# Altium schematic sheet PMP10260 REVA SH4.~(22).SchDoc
size 431 x 279 mm; Date: Not shown in title block; ApprovedBy: Not shown in title block; CheckedBy: Not shown in title block; Author: Not shown in title block; CompanyName: Not shown in title block; Engineer: Not shown in title block; Organization: Not shown in title block; Address1: Not shown in title block; Address2: Not shown in title block; Address3: Not shown in title block; Address4: Not shown in title block; DocumentNumber: 4; Revision: Use project parameter SCH_Rev; SheetNumber: 4; SheetTotal: 4; PageSetup: Record=PageOptions|CenterHorizontal=True|CenterVertical=True|PrintScale=1.00|XCorrection=1.00|YCorrection=1.00|PrintKind=0|BorderSize=5000000|LeftOffset=0|BottomOffset=0|Orientation=2|PaperLength=1000|PaperWidth=1000|Scale=100|PaperSource=15|PrintQuality=600|MediaType=1|DitherType=10|PaperKind=Letter|PrintScaleMode=1
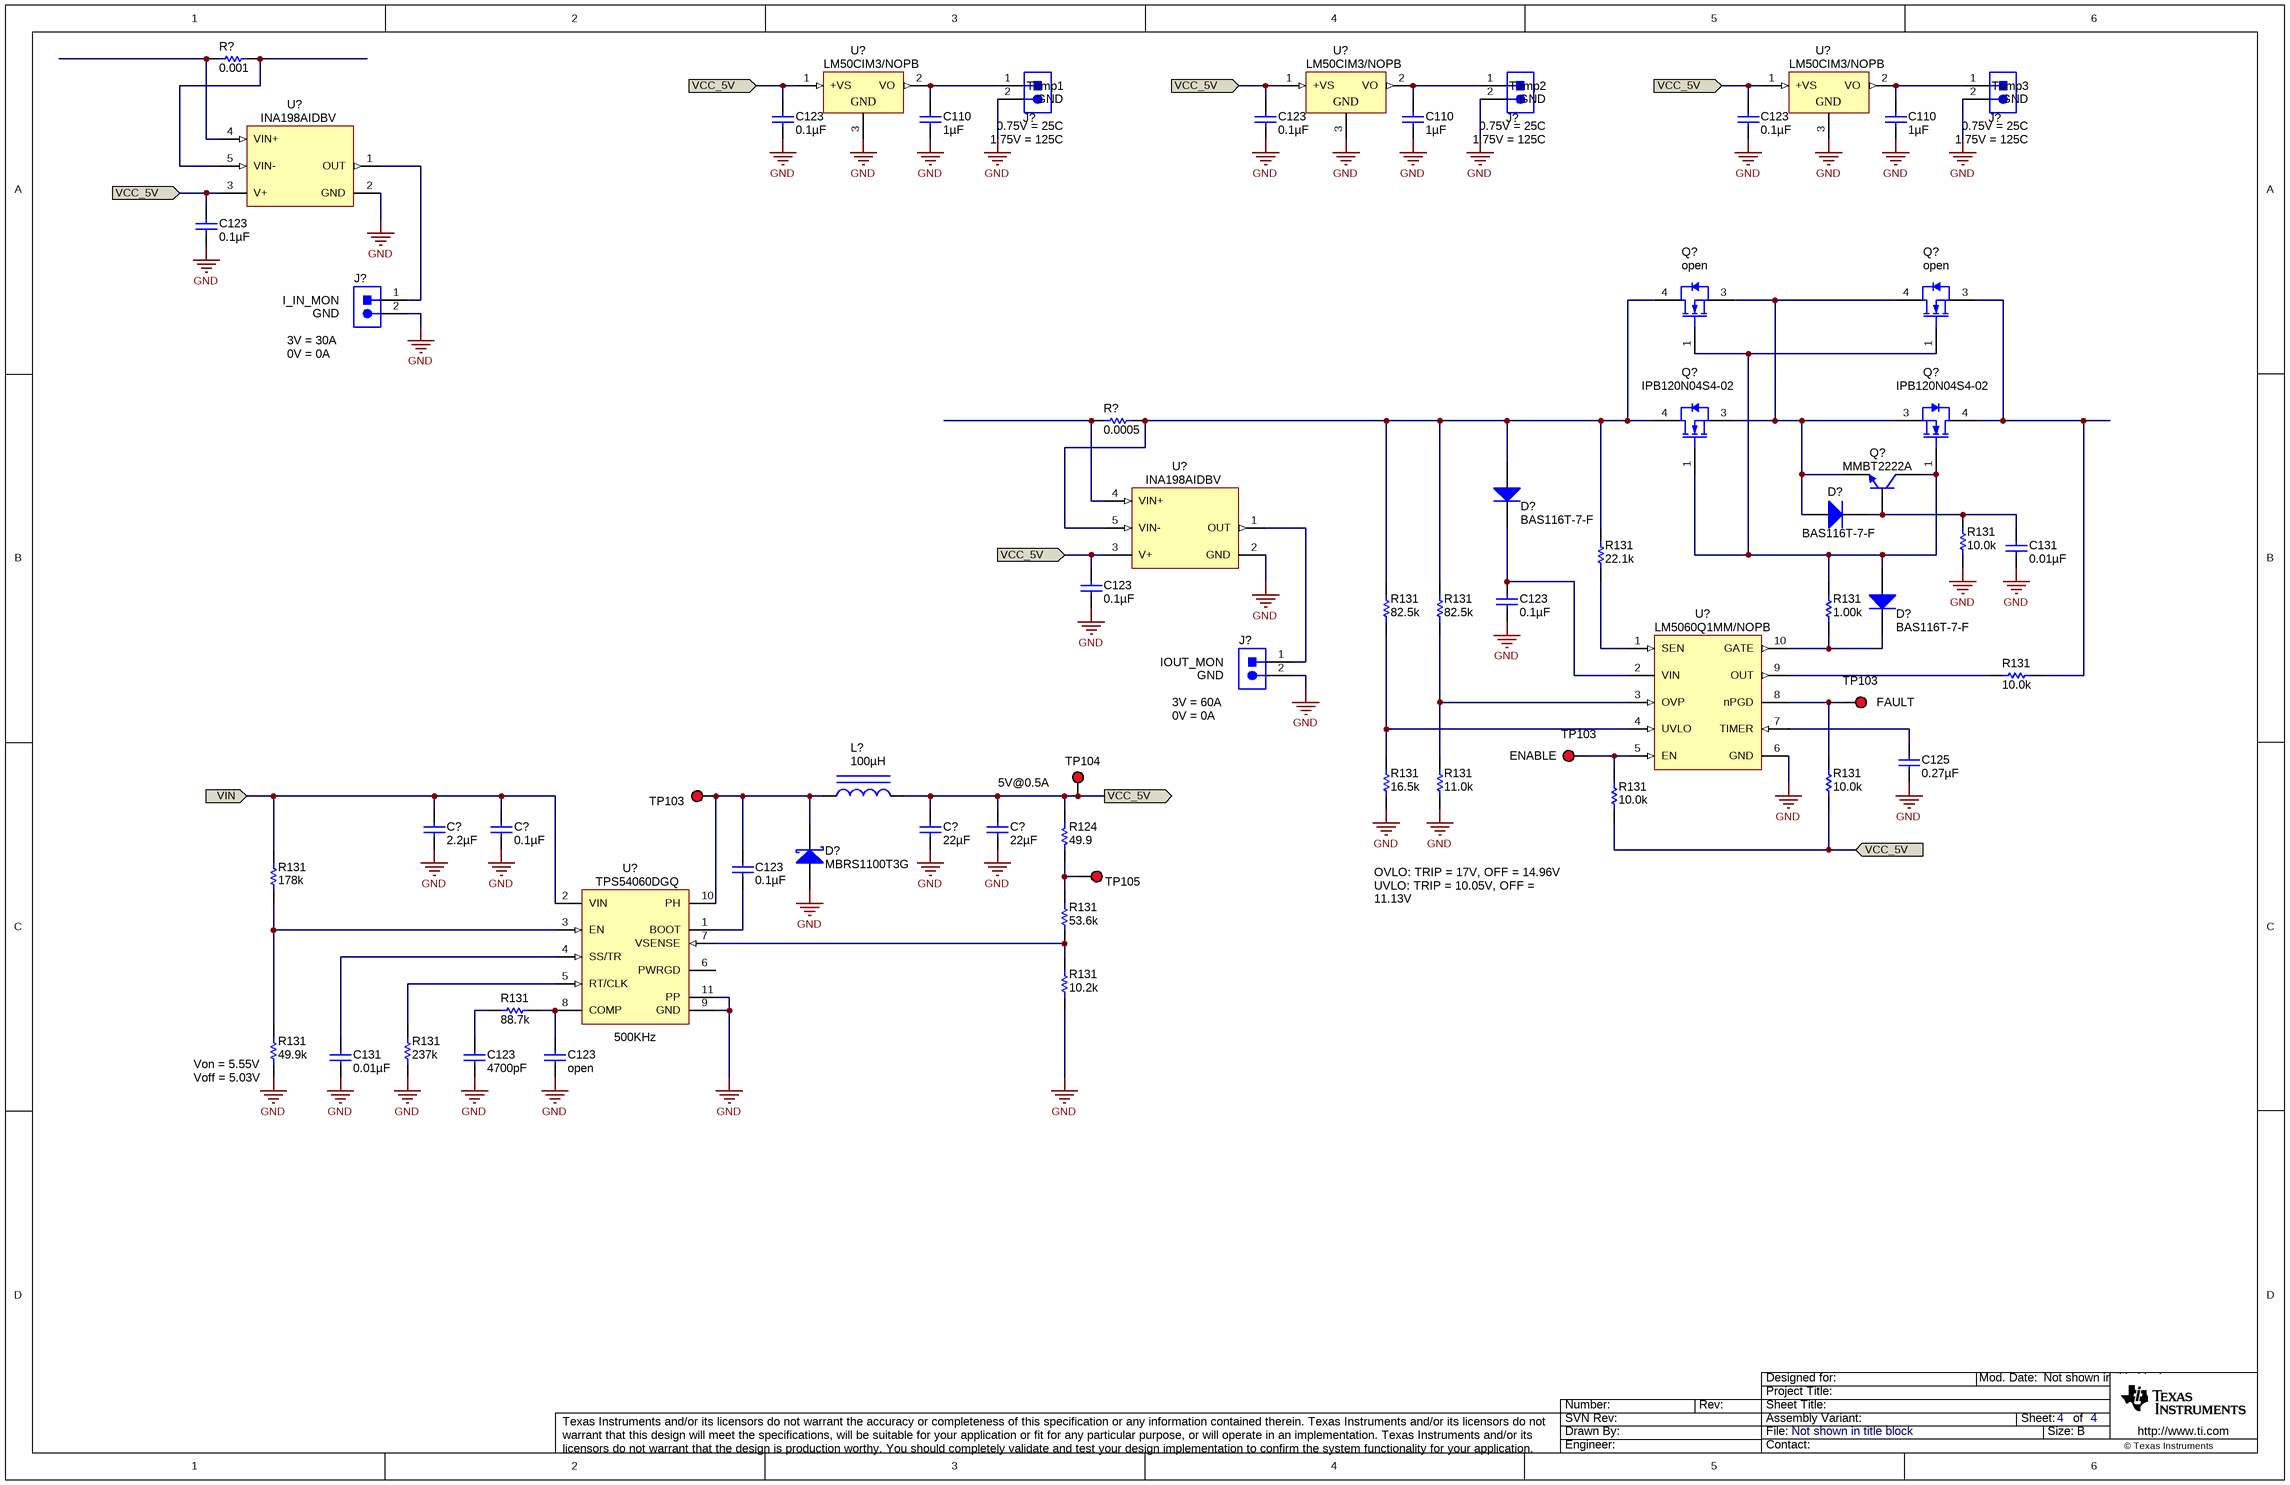
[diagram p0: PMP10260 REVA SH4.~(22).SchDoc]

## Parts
(Parts that share a designator on the sheet are numbered #1, #2 ... from top to bottom, then left to right.)
C110#1  ValueDisplayed: 1µF  [0603L]  (hidden comment: C1608X7R1E105K080AB)
C110#2  ValueDisplayed: 1µF  [0603L]  (hidden comment: C1608X7R1E105K080AB)
C110#3  ValueDisplayed: 1µF  [0603L]  (hidden comment: C1608X7R1E105K080AB)
C123#1  ValueDisplayed: 0.1µF  [0603L]  (hidden comment: C1608X7R1H104K)
C123#2  ValueDisplayed: 0.1µF  [0603L]  (hidden comment: C1608X7R1H104K)
C123#3  ValueDisplayed: 0.1µF  [0603L]  (hidden comment: C1608X7R1H104K)
C123#4  ValueDisplayed: 0.1µF  [0603L]  (hidden comment: C1608X7R1H104K)
C123#5  ValueDisplayed: 0.1µF  [0603L]  (hidden comment: C1608X7R1H104K)
C123#6  ValueDisplayed: 0.1µF  [0603L]  (hidden comment: C1608X7R1H104K)
C123#7  ValueDisplayed: 0.1µF  [0603L]  (hidden comment: C1608X7R1H104K)
C123#8  ValueDisplayed: 4700pF  [0603]  (hidden comment: C1608C0G1H472J)
C123#9  ValueDisplayed: open  [0603L]
C125  ValueDisplayed: 0.27µF  [0805_HV]  (hidden comment: 0805YC274KAT2A)
C131#1  ValueDisplayed: 0.01µF  [0603]  (hidden comment: C1608X7R1H103K)
C131#2  ValueDisplayed: 0.01µF  [0603]  (hidden comment: C1608X7R1H103K)
C?#1  ValueDisplayed: 2.2µF  [1210]  (hidden comment: GRM32ER72A225KA35L)
C?#2  ValueDisplayed: 0.1µF  [0603]  (hidden comment: GRM188R72A104KA35D)
C?#3  ValueDisplayed: 22µF  [1210]  (hidden comment: C3225X7R1C226M)
C?#4  ValueDisplayed: 22µF  [1210]  (hidden comment: C3225X7R1C226M)
D?#1  BAS116T-7-F  [SOT-523]
D?#2  BAS116T-7-F  [SOT-523]
D?#3  BAS116T-7-F  [SOT-523]
D?#4  MBRS1100T3G  [SMB]
J?#1  PEC02SAAN  [CONN_PEC02SAAN]  (value not drawn)
J?#2  PEC02SAAN  [CONN_PEC02SAAN]  (value not drawn)
J?#3  PEC02SAAN  [CONN_PEC02SAAN]  (value not drawn)
J?#4  PEC02SAAN  [CONN_PEC02SAAN]  (value not drawn)
J?#5  PEC02SAAN  [CONN_PEC02SAAN]  (value not drawn)
L?  ValueDisplayed: 100µH  [MSS1048]  (hidden comment: MSS1048-104MLB)
Q?#1  open  [DDPAK]
Q?#2  open  [DDPAK]
Q?#3  IPB120N04S4-02  [DDPAK]
Q?#4  IPB120N04S4-02  [DDPAK]
Q?#5  MMBT2222A  [SOT-23]
R124  value 49.9  [0603]  (hidden comment: CRCW060349R9FKEA)
R131#1  value 10.0k  [0603]  (hidden comment: CRCW060310K0FKEA)
R131#2  value 22.1k  [0603]  (hidden comment: CRCW060322K1FKEA)
R131#3  value 82.5k  [0603]  (hidden comment: CRCW060382K5FKEA)
R131#4  value 82.5k  [0603]  (hidden comment: CRCW060382K5FKEA)
R131#5  value 1.00k  [0603]  (hidden comment: CRCW06031K00FKEA)
R131#6  value 10.0k  [0603]  (hidden comment: CRCW060310K0FKEA)
R131#7  value 16.5k  [0603]  (hidden comment: CRCW060316K5FKEA)
R131#8  value 11.0k  [0603]  (hidden comment: CRCW060311K0FKEA)
R131#9  value 10.0k  [0603]  (hidden comment: CRCW060310K0FKEA)
R131#10  value 10.0k  [0603]  (hidden comment: CRCW060310K0FKEA)
R131#11  value 178k  [0603]  (hidden comment: CRCW0603178KFKEA)
R131#12  value 53.6k  [0603]  (hidden comment: CRCW060353K6FKEA)
R131#13  value 10.2k  [0603]  (hidden comment: CRCW060310K2FKEA)
R131#14  value 88.7k  [0603]  (hidden comment: CRCW060388K7FKEA)
R131#15  value 49.9k  [0603]  (hidden comment: CRCW060349K9FKEA)
R131#16  value 237k  [0603]  (hidden comment: CRCW0603237KFKEA)
R?#1  value 0.001  [CSS2725_0005]  (hidden comment: CSS2725FT1L00)
R?#2  value 0.0005  [CSS2725_0005]  (hidden comment: CSS2725FTL500)
TP103#1  5010  [Keystone5010]  (value not drawn)
TP103#2  5010  [Keystone5010]  (value not drawn)
TP103#3  5010  [Keystone5010]  (value not drawn)
TP104  5010  [Keystone5010]  (value not drawn)
TP105  5010  [Keystone5010]  (value not drawn)
U?#1  LM50CIM3/NOPB  [MF03A_N]
U?#2  LM50CIM3/NOPB  [MF03A_N]
U?#3  LM50CIM3/NOPB  [MF03A_N]
U?#4  INA198AIDBV  [DBV0005A_N]
U?#5  INA198AIDBV  [DBV0005A_N]
U?#6  LM5060Q1MM/NOPB  [MUB10A_N]
U?#7  TPS54060DGQ  [DGQ0010D_N]

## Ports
VCC_5V, VIN

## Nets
GND: C110#1.2 C110#2.2 C110#3.2 C123#1.2 C123#2.2 C123#3.2 C123#4.2 C123#5.2 C123#6.2 C123#8.2 C123#9.2 C125.2 C131#1.2 C131#2.2 C?#1.2 C?#2.2 C?#3.2 C?#4.2 D?#4.2(A) J?#1.2 J?#2.2 J?#3.2 J?#4.2 J?#5.2 R131#1.1 R131#7.1 R131#8.1 R131#13.1 R131#15.1 R131#16.1 U?#1.3(GND) U?#2.3(GND) U?#3.3(GND) U?#4.2(GND) U?#5.2(GND) U?#6.6(GND) U?#7.9(GND) U?#7.11(PP)
VCC_5V: C123#1.1 C123#2.1 C123#3.1 C123#4.1 C123#5.1 C?#3.1 C?#4.1 L?.2 R124.2 R131#9.1 R131#10.1 TP104.1 U?#1.1(+VS) U?#2.1(+VS) U?#3.1(+VS) U?#4.3(V+) U?#5.3(V+) ; port VCC_5V
VIN: C?#1.1 C?#2.1 R131#11.2 U?#7.2(VIN) ; port VIN
NetC110#1_1: C110#1.1 J?#1.1 U?#1.2(VO)
NetC110#2_1: C110#2.1 J?#2.1 U?#2.2(VO)
NetC110#3_1: C110#3.1 J?#3.1 U?#3.2(VO)
NetC123#6_1: C123#6.1 D?#1.3(K) U?#6.2(VIN)
NetC123#7_1: C123#7.1 D?#4.1(K) L?.1 TP103#3.1 U?#7.10(PH)
NetC123#7_2: C123#7.2 U?#7.1(BOOT)
NetC123#8_1: C123#8.1 R131#14.2
NetC123#9_1: C123#9.1 R131#14.1 U?#7.8(COMP)
NetC125_1: C125.1 U?#6.7(TIMER)
NetC131#1_1: C131#1.1 D?#2.3(K) Q?#5.1(B) R131#1.2
NetC131#2_1: C131#2.1 U?#7.4(SS/TR)
NetD?#1_1: D?#1.1(A) Q?#1.4(D) Q?#3.4(D) R131#2.2 R131#3.2 R131#4.2 R?#2.2 U?#5.5(VIN-)
NetD?#2_1: D?#2.1(A) Q?#1.3(S) Q?#2.4(D) Q?#3.3(S) Q?#4.3(S) Q?#5.2(E)
NetD?#3_1: D?#3.1(A) Q?#1.1(G) Q?#2.1(G) Q?#3.1(G) Q?#4.1(G) Q?#5.3(C) R131#5.1
NetD?#3_3: D?#3.3(K) R131#5.2 U?#6.10(GATE)
NetJ?#4_1: J?#4.1 U?#4.1(OUT)
NetJ?#5_1: J?#5.1 U?#5.1(OUT)
NetQ?#2_3: Q?#2.3(S) Q?#4.4(D) R131#6.1
NetR124_1: R124.1 R131#12.2 TP105.1
NetR131#2_1: R131#2.1 U?#6.1(SEN)
NetR131#3_1: R131#3.1 R131#7.2 U?#6.4(UVLO)
NetR131#4_1: R131#4.1 R131#8.2 U?#6.3(OVP)
NetR131#6_2: R131#6.2 U?#6.9(OUT)
NetR131#9_2: R131#9.2 TP103#1.1 U?#6.8(nPGD)
NetR131#10_2: R131#10.2 TP103#2.1 U?#6.5(EN)
NetR131#11_1: R131#11.1 R131#15.2 U?#7.3(EN)
NetR131#12_1: R131#12.1 R131#13.2 U?#7.7(VSENSE)
NetR131#16_2: R131#16.2 U?#7.5(RT/CLK)
NetR?#1_1: R?#1.1 U?#4.4(VIN+)
NetR?#1_2: R?#1.2 U?#4.5(VIN-)
NetR?#2_1: R?#2.1 U?#5.4(VIN+)

Not connected (* = marked no-connect by the designer): U?#7 6(PWRGD)

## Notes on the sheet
- (near J?#1) Temp1
- (near J?#1) GND
- (near J?#2) Temp2
- (near J?#2) GND
- (near J?#3) Temp3
- (near J?#3) GND
- (near J?#1) 0.75V = 25C
- (near J?#1) 1.75V = 125C
- (near J?#2) 0.75V = 25C
- (near J?#2) 1.75V = 125C
- (near J?#3) 0.75V = 25C
- (near J?#3) 1.75V = 125C
- (near J?#4) I_IN_MON
- (near J?#4) 3V = 30A
- 0V = 0A
- (near J?#4) GND
- (near J?#5) 3V = 60A
- (near J?#5) IOUT_MON
- (near J?#5) GND
- (near TP103#1) FAULT
- (near TP103#2) ENABLE
- 5V@0.5A
- OVLO: TRIP = 17V, OFF = 14.96V
  UVLO: TRIP = 10.05V, OFF = 11.13V
  OC = 65A/Hot
- (near U?#7) 500KHz
- (near R131#15) Von = 5.55V
- (near R131#15) Voff = 5.03V

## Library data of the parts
C110#1-C110#3 = C1608X7R1E105K080AB: CAP, CERM, 1uF, 25V, +/-10%, X7R, 0603; Manufacturer: TDK; Polarized: N; CompType: Capacitor; U/M: EA; Cap_F: 0.000001; Tolerance_%: 10; Value1: Unknown; VDC_V: 25; TaMin_C: -55; TaMax_C: 125; Cap_Case: 0603
C123#1-C123#7 = C1608X7R1H104K: CAP, CERM, 0.1uF, 50V, +/-10%, X7R, 0603; Manufacturer: TDK; Polarized: N; CompType: Capacitor; U/M: EA; Cap_F: 0.0000001; Tolerance_%: 10; ESR_Ohm: 0.017; Value1: 0.017 ohm; VDC_V: 50; TaMin_C: -55; TaMax_C: 125; Cap_Case: 0603
C123#8 = C1608C0G1H332J: CAP, CERM, 4700pF, 50V, +/-5%, C0G/NP0, 0603; Manufacturer: TDK; Polarized: N; CompType: Capacitor; Value: 3300pF; U/M: EA; Cap_F: 0.0000000033; Tolerance_%: 5; ESR_Ohm: 0.0309; Value1: 0.0309 ohm; VDC_V: 50; TaMin_C: -55; TaMax_C: 125
C123#9 = C1608X7R1H104K: CAP, open, 0603; Polarized: N; CompType: Capacitor; U/M: EA; Cap_F: 0.0000001; Tolerance_%: 10; ESR_Ohm: 0.017; TempCo: X7R; TaMin_C: -55; TaMax_C: 125; Cap_Case: 0603
C125 = 0805YC274KAT2A: CAP, CERM, 0.27uF, 16V, +/-10%, X7R, 0805; Manufacturer: AVX; Polarized: N; CompType: Capacitor; U/M: EA; Cap_F: 0.00000027; Tolerance_%: 10; ESR_Ohm: 0.015; Value1: 0.015 ohm; VDC_V: 16; TaMin_C: -55; TaMax_C: 125; Cap_Case: 0805
C131#1 C131#2 = C1608X7R1H103K: CAP, CERM, 0.01uF, 50V, +/-10%, X7R, 0603; Manufacturer: TDK; Polarized: N; CompType: Capacitor; U/M: EA; Cap_F: 0.00000001; Tolerance_%: 10; ESR_Ohm: 0.0539; Value1: 0.0539 ohm; VDC_V: 50; TaMin_C: -55; TaMax_C: 125
C?#1 = GRM32ER72A225KA35L: CAP, CERM, 2.2uF, 100V, +/-10%, X7R, 1210; Manufacturer: MuRata; Polarized: N; CompType: Capacitor; U/M: EA; Cap_F: 0.0000022; Tolerance_%: 10; ESR_Ohm: 0.007; Value1: 0.007 ohm; VDC_V: 100; IRMS_A: 4.4; TaMin_C: -55; TaMax_C: 125
C?#2 = GRM188R72A104KA35D: CAP, CERM, 0.1uF, 100V, +/-10%, X7R, 0603; Manufacturer: MuRata; Polarized: N; CompType: Capacitor; U/M: EA; Cap_F: 0.0000001; Tolerance_%: 10; Value1: Unknown; VDC_V: 100; TaMin_C: -55; TaMax_C: 125
C?#3 C?#4 = C3225X7R1C226M: CAP, CERM, 22uF, 16V, +/-20%, X7R, 1210; Manufacturer: TDK; Polarized: N; CompType: Capacitor; U/M: EA; Cap_F: 0.000022; Tolerance_%: 20; ESR_Ohm: 0.002; Value1: 0.002 ohm; VDC_V: 16; IRMS_A: 8.11; TaMin_C: -55; TaMax_C: 125
D?#1-D?#3 = BAS116T-7-F: Diode, Switching, 85V, 0.215A, SOT-523; Manufacturer: Diodes Inc.; U/M: EA; Vf_V: 1.25; Value2: 1.25V; Io_A: 0.215; Vr_V: 85; TJmax_C: 150
D?#4 = MBRS1100T3G: Diode, Schottky, 100V, 1A, SMB; Manufacturer: ON Semiconductor; U/M: EA; Vf_V: 0.75; Value2: 0.75V; Io_A: 1; Vr_V: 100; TJmax_C: 150; RJC_CperW: 22
J?#1-J?#5 = PEC02SAAN: Header, 100mil, 2x1, Tin, TH; Manufacturer: Sullins Connector Solutions; SymbolCreator: a0412235; U/M: EA
L? = MSS1048-104MLB: Inductor, Shielded Drum Core, Ferrite, 100uH, 1.36A, 0.25 ohm, SMD; Manufacturer: Coilcraft; Ind_H: 100.0E-6; Imax_A: 1.36; Irms: 1.48A @ 40C rise; Isat: 1.36A @ 30% inductance drop; DCR_ohm: 0.25
Q?#1 Q?#2 = IPB100N10S3-05: MOSFET, open, DDPAK; Alternate Manufacturer: None; U/M: EA; ChType: N; Value1: ? ohm; IdsMax_A: 100
Q?#3 Q?#4 = IPB100N10S3-05: MOSFET, N-CH, 40V, 120A, DDPAK; Manufacturer: Infineon Technologies; Alternate Manufacturer: None; U/M: EA; ChType: N; VdsMax_V: 40; Value1: ? ohm; Vgs_V: 20; IdsMax_A: 100
Q?#5 = MMBT2222A, Fairchild Semiconductor: Transistor, NPN, 40V, 0.15A, SOT-23; CompType: BJT; PNP: 0; NPN: 1; Vceo_V: 40; Vcesat1_V: 0.3; Value: 0.3V; IcRated_A: 0.15; HfeMax: 300; TaMin_C: -55; TaMax_C: 150; U/M: EA
R124 = CRCW060349R9FKEA: RES, 49.9 ohm, 1%, 0.1W, 0603; Manufacturer: Vishay-Dale; CompType: Resistor; Value_Code: 49R9; Tolerance_%: 1; Power_W: 0.1; VDC_V: 75; TempCo: 100 ppm/C; EIA_Code: E96; U/M: EA
R131#1 R131#6 R131#9 R131#10 = CRCW060310K0FKEA: RES, 10.0k ohm, 1%, 0.1W, 0603; Manufacturer: Vishay-Dale; CompType: Resistor; Res_ohm: 10000; Value_Code: 10k0; Tolerance_%: 1; Power_W: 0.1; VDC_V: 75; TempCo: 100 ppm/C; EIA_Code: E96; U/M: EA
R131#2 = CRCW060322K1FKEA: RES, 22.1k ohm, 1%, 0.1W, 0603; Manufacturer: Vishay-Dale; CompType: Resistor; Res_ohm: 22100; Value_Code: 22k1; Tolerance_%: 1; Power_W: 0.1; VDC_V: 75; TempCo: 100 ppm/C; EIA_Code: E96; U/M: EA
R131#3 R131#4 = CRCW060382K5FKEA: RES, 82.5k ohm, 1%, 0.1W, 0603; Manufacturer: Vishay-Dale; CompType: Resistor; Res_ohm: 82500; Value_Code: 82k5; Tolerance_%: 1; Power_W: 0.1; VDC_V: 75; TempCo: 100 ppm/C; EIA_Code: E96; U/M: EA
R131#5 = CRCW06031K00FKEA: RES, 1.00k ohm, 1%, 0.1W, 0603; Manufacturer: Vishay-Dale; CompType: Resistor; Res_ohm: 1000; Value_Code: 1k00; Tolerance_%: 1; Power_W: 0.1; VDC_V: 75; TempCo: 100 ppm/C; EIA_Code: E96; U/M: EA
R131#7 = CRCW060316K5FKEA: RES, 16.5k ohm, 1%, 0.1W, 0603; Manufacturer: Vishay-Dale; CompType: Resistor; Res_ohm: 16500; Value_Code: 16k5; Tolerance_%: 1; Power_W: 0.1; VDC_V: 75; TempCo: 100 ppm/C; EIA_Code: E96; U/M: EA
R131#8 = CRCW060311K0FKEA: RES, 11.0k ohm, 1%, 0.1W, 0603; Manufacturer: Vishay-Dale; CompType: Resistor; Res_ohm: 11000; Value_Code: 11k0; Tolerance_%: 1; Power_W: 0.1; VDC_V: 75; TempCo: 100 ppm/C; EIA_Code: E96; U/M: EA
R131#11 = CRCW0603178KFKEA: RES, 178k ohm, 1%, 0.1W, 0603; Manufacturer: Vishay-Dale; CompType: Resistor; Res_ohm: 178000; Tolerance_%: 1; Power_W: 0.1; VDC_V: 75; TempCo: 100 ppm/C; EIA_Code: E96; U/M: EA
R131#12 = CRCW060353K6FKEA: RES, 53.6k ohm, 1%, 0.1W, 0603; Manufacturer: Vishay-Dale; CompType: Resistor; Res_ohm: 53600; Value_Code: 53k6; Tolerance_%: 1; Power_W: 0.1; VDC_V: 75; TempCo: 100 ppm/C; EIA_Code: E96; U/M: EA
R131#13 = CRCW060310K2FKEA: RES, 10.2k ohm, 1%, 0.1W, 0603; Manufacturer: Vishay-Dale; CompType: Resistor; Res_ohm: 10200; Value_Code: 10k2; Tolerance_%: 1; Power_W: 0.1; VDC_V: 75; TempCo: 100 ppm/C; EIA_Code: E96; U/M: EA
R131#14 = CRCW060388K7FKEA: RES, 88.7k ohm, 1%, 0.1W, 0603; Manufacturer: Vishay-Dale; CompType: Resistor; Res_ohm: 88700; Value_Code: 88k7; Tolerance_%: 1; Power_W: 0.1; VDC_V: 75; TempCo: 100 ppm/C; EIA_Code: E96; U/M: EA
R131#15 = CRCW060349K9FKEA: RES, 49.9k ohm, 1%, 0.1W, 0603; Manufacturer: Vishay-Dale; CompType: Resistor; Res_ohm: 49900; Value_Code: 49k9; Tolerance_%: 1; Power_W: 0.1; VDC_V: 75; TempCo: 100 ppm/C; EIA_Code: E96; U/M: EA
R131#16 = CRCW0603237KFKEA: RES, 237k ohm, 1%, 0.1W, 0603; Manufacturer: Vishay-Dale; CompType: Resistor; Res_ohm: 237000; Tolerance_%: 1; Power_W: 0.1; VDC_V: 75; TempCo: 100 ppm/C; EIA_Code: E96; U/M: EA
R?#1 = CSS2725FTL500: RES, 0.001 ohm, 1%, 4W, RES_2725; Manufacturer: Stackpole Electronics Inc; CompType: Resistor; Res_ohm: 0.0005; Value_Code: R001; Tolerance_%: 1; Power_W: 4; TempCo: 50 ppm/C; U/M: EA
R?#2 = CSS2725FTL500: RES, 0.0005 ohm, 1%, 4W, RES_2725; Manufacturer: Stackpole Electronics Inc; CompType: Resistor; Value_Code: R0005; Tolerance_%: 1; Power_W: 4; TempCo: 50 ppm/C; U/M: EA
TP103#1-TP103#3 TP104 TP105 = 5010: Test Point, Multipurpose, Red, TH; Manufacturer: Keystone; CompType: Test Point Loop; U/M: EA
U?#1-U?#3 = LM50CIM3/NOPB: Single-Supply Centigrade Temperature Sensor, 3-pin SOT-23, Pb-Free; Manufacturer: Texas Instruments; PackageTopMarking: T5C*XTT; PowerWise: N; CompType: Temp Sensor IC
U?#4 U?#5 = INA198AIDBV: CURRENT SHUNT MONITOR -16V to +80V Common-Mode Range, DBV0005A; Alternate Manufacturer: None; Manufacturer: Texas Instruments; SymbolCreator: a0411947; CompType: IC; U/M: EA
U?#6 = LM5060Q1MM/NOPB: High-Side Protection Controller with Low Quiescent Current, 10-pin MSOP, Pb-Free; Manufacturer: National Semiconductor; PackageTopMarking: ZXTT*SZAB; PowerWise: N; CompType: Switcher
U?#7 = TPS54060DGQ: Buck Inverting Buck-Boost Step Down Regulator with 3.5 to 60 V Input and 0.8 to 58 V Output, -40 to 150 degC, 10-Pin MSOP-PowerPAD (DGQ), Green (RoHS & no Sb/Br); Manufacturer: Texas Instruments; Alternate Manufacturer: None; Alternate PartNumber: Equivalent; Duty Cycle(Max)(%): 98; Iout(Max)(A): 0.5; Iq(Typ)(mA): 0.116; Rating: Catalog; Regulated Outputs(#): 1; SubFamily: Step-Down Regulator; Switch Current Limit(Typ)(A): 0.6; Topology: Buck, Inverting Buck-Boost; Vin(Max)(V): 60; Vin(Min)(V): 3.5; Vout(Max)(V): 58; Vout(Min)(V): 0.8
